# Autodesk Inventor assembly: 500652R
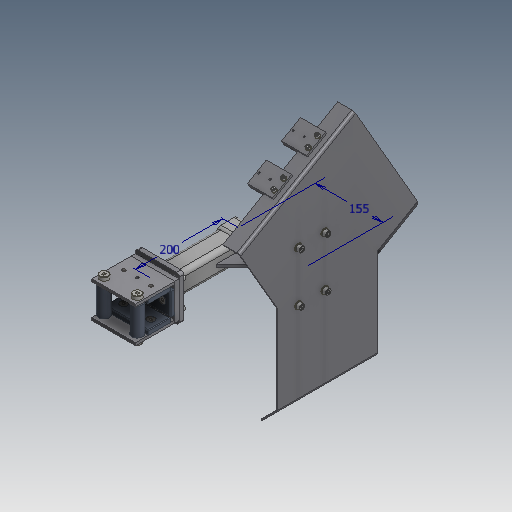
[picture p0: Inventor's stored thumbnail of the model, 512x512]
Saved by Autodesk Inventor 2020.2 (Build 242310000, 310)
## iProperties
Created: 2000-02
Part Number: 500652R
Document SubType Name: Assembly
Designer: sspink
Mass: 4880.34 g
Surface Area: 6473.94 cm^2
Volume: 1390.02 cm^3
Density: 3.51099 g/cm^3
Control State: 0
Master: False
Checked Out: False
Shininess: 0.0
Length Units: 11269
Angle Units: 11279
Time Units: 11290
Mass Units: 11283
Length Display Precision: 3
Angle Display Precision: 2
Compacted: True
Dimensions: 541,9x566,8x202,1 mm
Mass: 4,88 kg
DocNumber: 500652R.iam
Folder: 01 - Themengebiete\Simplification\01 - Packaging machine\
VDS_Category: 3D Komponenten
Density: 0.0
Volumn: 0.0
Area: 0.0
PropertySet Name: Model Information
Author: sspink
Revision Number: -
Title: 500652R
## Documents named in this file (15)
- D:\07 - DEMODATEN\OTX 2019 - Dataset - UPDATE - Dez2019\Designs\07-Packing machine\500652R.iam
- D:\07 - DEMODATEN\OTX 2019 - Dataset - UPDATE - Dez2019\Designs\07-Packing machine\500653.iam
- D:\07 - DEMODATEN\OTX 2019 - Dataset - UPDATE - Dez2019\Designs\07-Packing machine\Parts\ADSK-011631.ipt
- D:\07 - DEMODATEN\OTX 2019 - Dataset - UPDATE - Dez2019\Designs\07-Packing machine\Parts\ADSK-011632.ipt
- D:\07 - DEMODATEN\OTX 2019 - Dataset - UPDATE - Dez2019\Designs\07-Packing machine\Parts\ADSK-011728.ipt
- D:\07 - DEMODATEN\OTX 2019 - Dataset - UPDATE - Dez2019\Designs\07-Packing machine\Parts\ADSK-011624.ipt
- D:\07 - DEMODATEN\OTX 2019 - Dataset - UPDATE - Dez2019\Designs\07-Packing machine\Parts\ADSK-011664.ipt
- D:\07 - DEMODATEN\OTX 2019 - Dataset - UPDATE - Dez2019\Designs\07-Packing machine\500657.iam
- D:\07 - DEMODATEN\OTX 2019 - Dataset - UPDATE - Dez2019\Content Center Files\de-DE\ISO 10642(1)\ISO 10642 - M8x16.ipt
- D:\07 - DEMODATEN\OTX 2019 - Dataset - UPDATE - Dez2019\Content Center Files\de-DE\ISO 4032(1)\ISO 4032 - M10DIN EN.ipt
- D:\07 - DEMODATEN\OTX 2019 - Dataset - UPDATE - Dez2019\Content Center Files\de-DE\DIN 125-1  B\DIN 125-1 - B 8,4.ipt
- D:\07 - DEMODATEN\OTX 2019 - Dataset - UPDATE - Dez2019\Content Center Files\de-DE\ISO 4762(2)\ISO 4762 - M8 x 20ISO.ipt
- D:\07 - DEMODATEN\OTX 2019 - Dataset - UPDATE - Dez2019\Content Center Files\de-DE\ISO 4032(1)\ISO 4032 - M8DIN EN.ipt
- D:\07 - DEMODATEN\OTX 2019 - Dataset - UPDATE - Dez2019\Content Center Files\de-DE\DIN 125-1  B\DIN 125-1 - B 5,3.ipt
- D:\07 - DEMODATEN\OTX 2019 - Dataset - UPDATE - Dez2019\Content Center Files\de-DE\ISO 4762(2)\ISO 4762 - M5 x 12ISO.ipt
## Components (52 placed, 14 different names)
1. 500653:1 [sub-assembly] — Mate:1, Flush:2, Insert:1, Insert:2, Passend:24, Passend:25, Passend:26, Passend:27, Passend:28, Passend:29, Passend:30, Passend:31, Passend:32, Fluchtend:3, Passend:35, Passend:36, Passend:37, Passend:38, Passend:46, Passend:48
2. 500657:1 [sub-assembly] — Passend:24, Passend:25, Passend:26, Passend:50, Passend:56, Passend:58, Passend:60, Passend:79, Passend:80, Passend:81, Passend:83, Passend:85, Passend:87, Passend:89
3. ADSK-011631:1 — Passend:34, Fluchtend:3
4. ADSK-011631:2 — Passend:33, Passend:35
5. ADSK-011632:1 — Mate:1, Flush:2, Passend:27, Passend:28, Passend:29
6. ADSK-011632:2 — Passend:36, Passend:37, Passend:38
7. ADSK-011632:3 — Passend:30, Passend:31, Passend:32
8. ADSK-011728:1 — Insert:2, Passend:33
9. ADSK-011728:2 — Insert:1, Passend:34
10. ADSK-011624:2 — Passend:15, Passend:16, Passend:17, Passend:18, Passend:20, Passend:21, Passend:79, Passend:80, Passend:81
11. ADSK-011664:1 — Passend:15, Passend:16, Passend:20
12. ADSK-011664:2 — Passend:17, Passend:18, Passend:21
13. DIN 125-1 B B 8,4:7 — Passend:83
14. DIN 125-1 B B 8,4:8 — Passend:85
15. DIN 125-1 B B 8,4:9 — Passend:87
16. DIN 125-1 B B 8,4:10 — Passend:89
17. DIN 125-1 B B 8,4:11
18. DIN 125-1 B B 8,4:12
19. DIN 125-1 B B 8,4:13
20. DIN 125-1 B B 8,4:14
21. DIN EN 24032 M8:1
22. DIN EN 24032 M8:2
23. DIN EN 24032 M8:3
24. DIN EN 24032 M8:4
25. ISO 4762 M8 x 20:7
26. ISO 4762 M8 x 20:8
27. ISO 4762 M8 x 20:9
28. ISO 4762 M8 x 20:10
29. ISO 4762 M5 x 12:4
30. ISO 4762 M5 x 12:3
31. ISO 4762 M5 x 12:2
32. ISO 4762 M5 x 12:1
33. DIN 125-1 B B 5,3:4
34. DIN 125-1 B B 5,3:3
35. DIN 125-1 B B 5,3:2
36. DIN 125-1 B B 5,3:1
37. ISO 4762 M8 x 20:6 — Passend:72
38. ISO 4762 M8 x 20:5 — Passend:70
39. ISO 4762 M8 x 20:4 — Passend:68
40. ISO 4762 M8 x 20:1 — Passend:62
41. DIN 125-1 B B 8,4:6 — Passend:60
42. DIN 125-1 B B 8,4:5 — Passend:58
43. DIN 125-1 B B 8,4:4 — Passend:56
44. DIN 125-1 B B 8,4:1 — Passend:50, Passend:62, Passend:68, Passend:70, Passend:72
45. ISO 10642 M8x16:1
46. ISO 10642 M8x16:2
47. ISO 10642 M8x16:3
48. ISO 10642 M8x16:4
49. ISO 10642 M8x16:5
50. ISO 10642 M8x16:6
51. DIN EN 24032 M10:1 — Passend:46
52. DIN EN 24032 M10:2 — Passend:48
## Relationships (43: Mate 39, Flush 2, Insert 2)
- Mate:1: 500653:1 ↔ ADSK-011632:1
- Flush:2: 500653:1 ↔ ADSK-011632:1
- Insert:1: 500653:1 ↔ ADSK-011728:2
- Insert:2: 500653:1 ↔ ADSK-011728:1
- Passend:15 [Mate]: ADSK-011624:2 ↔ ADSK-011664:1
- Passend:16 [Mate]: ADSK-011624:2 ↔ ADSK-011664:1
- Passend:17 [Mate]: ADSK-011624:2 ↔ ADSK-011664:2
- Passend:18 [Mate]: ADSK-011624:2 ↔ ADSK-011664:2
- Passend:20 [Mate]: ADSK-011624:2 ↔ ADSK-011664:1
- Passend:21 [Mate]: ADSK-011624:2 ↔ ADSK-011664:2
- Passend:24 [Mate]: 500653:1 ↔ 500657:1
- Passend:25 [Mate]: 500653:1 ↔ 500657:1
- Passend:26 [Mate]: 500653:1 ↔ 500657:1
- Passend:27 [Mate]: 500653:1 ↔ ADSK-011632:1
- Passend:28 [Mate]: 500653:1 ↔ ADSK-011632:1
- Passend:29 [Mate]: 500653:1 ↔ ADSK-011632:1
- Passend:30 [Mate]: 500653:1 ↔ ADSK-011632:3
- Passend:31 [Mate]: 500653:1 ↔ ADSK-011632:3
- Passend:32 [Mate]: 500653:1 ↔ ADSK-011632:3
- Passend:33 [Mate]: ADSK-011631:2 ↔ ADSK-011728:1
- Passend:34 [Mate]: ADSK-011631:1 ↔ ADSK-011728:2
- Fluchtend:3 [Flush]: 500653:1 ↔ ADSK-011631:1
- Passend:35 [Mate]: 500653:1 ↔ ADSK-011631:2
- Passend:36 [Mate]: 500653:1 ↔ ADSK-011632:2
- Passend:37 [Mate]: 500653:1 ↔ ADSK-011632:2
- Passend:38 [Mate]: 500653:1 ↔ ADSK-011632:2
- Passend:46 [Mate]: 500653:1 ↔ DIN EN 24032 M10:1
- Passend:48 [Mate]: 500653:1 ↔ DIN EN 24032 M10:2
- Passend:50 [Mate]: 500657:1 ↔ DIN 125-1 B B 8,4:1
- Passend:56 [Mate]: 500657:1 ↔ DIN 125-1 B B 8,4:4
- Passend:58 [Mate]: 500657:1 ↔ DIN 125-1 B B 8,4:5
- Passend:60 [Mate]: 500657:1 ↔ DIN 125-1 B B 8,4:6
- Passend:62 [Mate]: ISO 4762 M8 x 20:1 ↔ DIN 125-1 B B 8,4:1
- Passend:68 [Mate]: ISO 4762 M8 x 20:4 ↔ DIN 125-1 B B 8,4:1
- Passend:70 [Mate]: ISO 4762 M8 x 20:5 ↔ DIN 125-1 B B 8,4:1
- Passend:72 [Mate]: ISO 4762 M8 x 20:6 ↔ DIN 125-1 B B 8,4:1
- Passend:79 [Mate]: 500657:1 ↔ ADSK-011624:2
- Passend:80 [Mate]: 500657:1 ↔ ADSK-011624:2
- Passend:81 [Mate]: 500657:1 ↔ ADSK-011624:2
- Passend:83 [Mate]: 500657:1 ↔ DIN 125-1 B B 8,4:7
- Passend:85 [Mate]: 500657:1 ↔ DIN 125-1 B B 8,4:8
- Passend:87 [Mate]: 500657:1 ↔ DIN 125-1 B B 8,4:9
- Passend:89 [Mate]: 500657:1 ↔ DIN 125-1 B B 8,4:10
